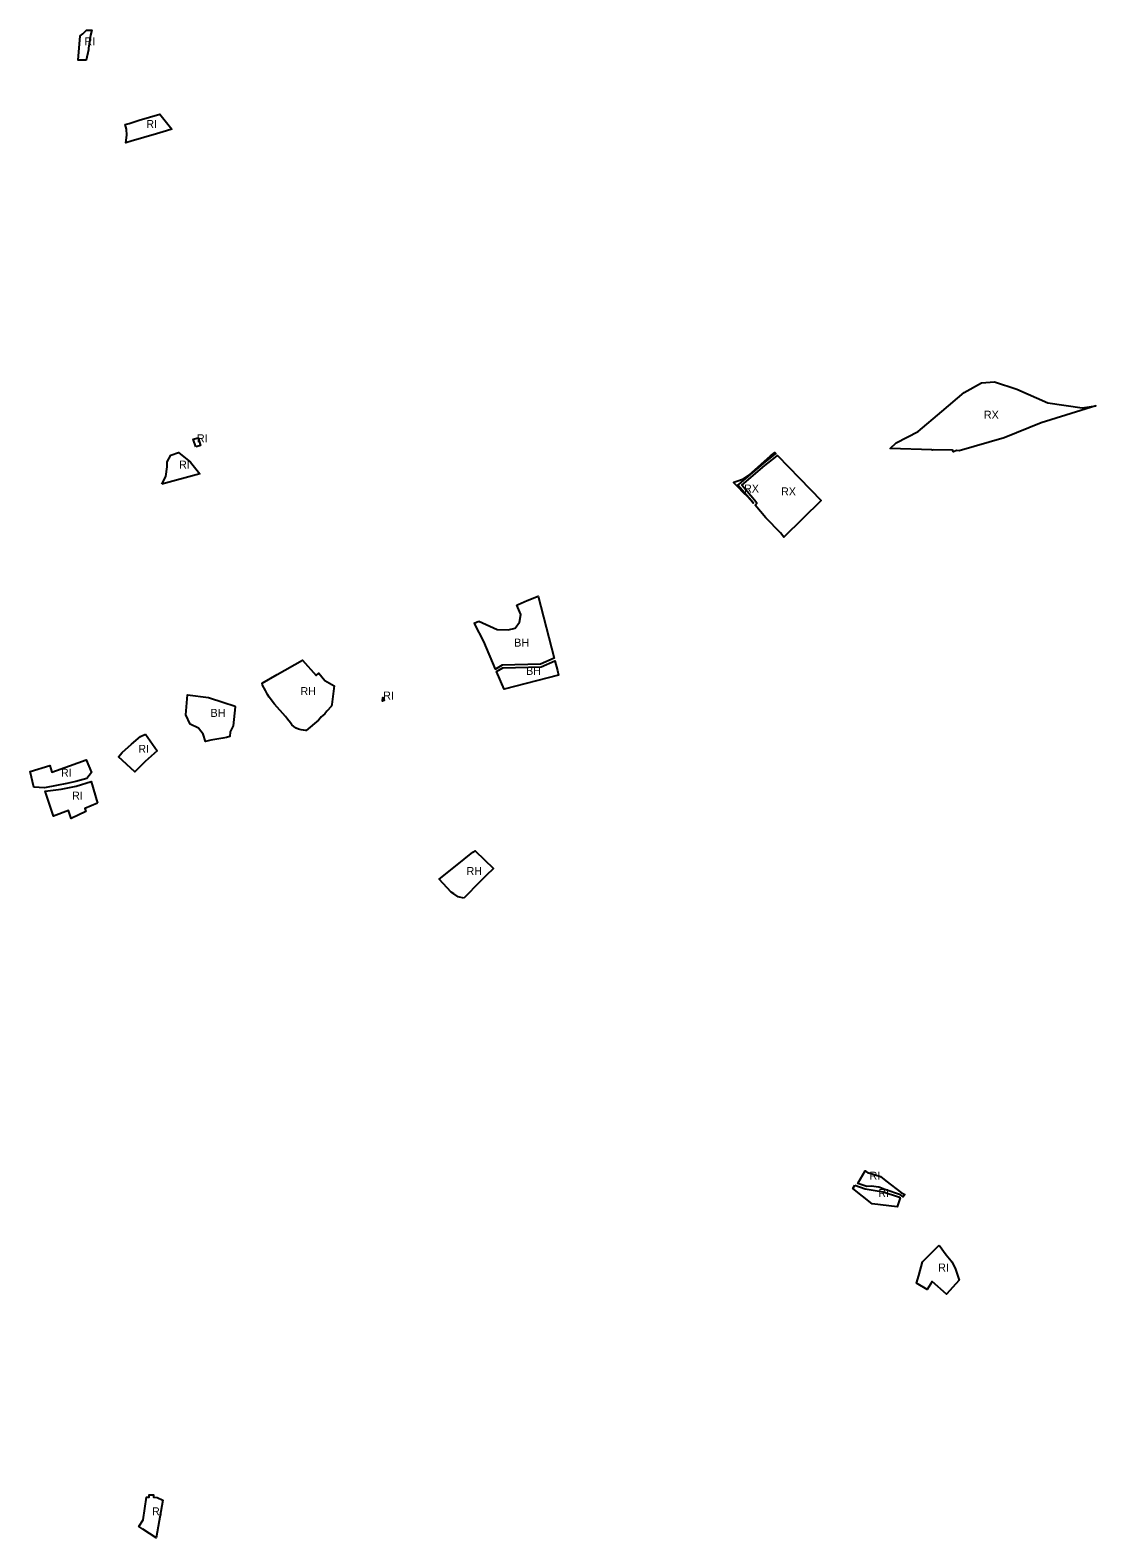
# Model space of a CAD drawing. Extents: x -477010 to -466219, y -1158799 to -1150161.
# Drawn here: x -470055 to -468854, y -1154442 to -1152743 of the extents above; entities that cross this region are included whole.
import ezdxf

# ---------------------------------------------------------------- set-up
doc = ezdxf.new("R2010")
doc.units = 0
for name, color, linetype in [('16', 7, 'Continuous'), ('19', 7, 'Continuous'), ('25', 7, 'Continuous'), ('4', 7, 'Continuous')]:
    doc.layers.add(name, color=color, linetype=linetype)

msp = doc.modelspace()

# ---------------------------------------------------------------- linework, layer by layer
at = {"layer": '16'}
for points in [[(-469720.54, -1153510.21), (-469723.07, -1153513.06), (-469725.155, -1153514.929), (-469726.93, -1153516.52), (-469727.816, -1153517.531), (-469730.11, -1153520.15), (-469744.05, -1153531.89), (-469744.58, -1153531.81), (-469747.07, -1153531.46), (-469749.61, -1153531.09), (-469752.58, -1153530.33), (-469755.37, -1153529.22), (-469757.82, -1153527.25), (-469760.03, -1153525.33), (-469761.57, -1153523.16), (-469765.13, -1153518.88), (-469767.37, -1153516.16), (-469779.49, -1153502.3), (-469785.57, -1153494.24), (-469787.54, -1153491.35), (-469789.85, -1153486.93), (-469792.99, -1153480.68), (-469793.44, -1153478.47), (-469776.53, -1153468.6), (-469748.05, -1153452.39), (-469732.51, -1153469.78), (-469729.53, -1153467.14), (-469723.09, -1153475.3), (-469712.23, -1153481.51), (-469715.09, -1153502.44), (-469715.27, -1153504.3)], [(-469566.15, -1153720.69), (-469572.52, -1153719.17), (-469577.58, -1153716.01), (-469580.51, -1153714.16), (-469594.04, -1153699.49), (-469592.71, -1153698.22), (-469566, -1153676.65), (-469556.08, -1153669.1), (-469553.54, -1153667.48), (-469532.85, -1153687.29), (-469541.02, -1153695.16), (-469548.02, -1153701.9)]]:
    msp.add_lwpolyline(points, close=True, dxfattribs=at)
at = {"layer": '19'}
for points in [[(-469995.71, -1152746.77), (-469991.28, -1152742.81), (-469985.48, -1152742.62), (-469986.82, -1152748.2), (-469989.21, -1152763.01), (-469989.19, -1152764.92), (-469991.66, -1152776.5), (-470000.793, -1152776.5), (-469998.48, -1152749.11)], [(-469931.93, -1152844.23), (-469908.87, -1152837.23), (-469895.2, -1152854.33), (-469901.47, -1152856.18), (-469912.71, -1152859.48), (-469941.19, -1152867.85), (-469946.01, -1152869.26), (-469946.95, -1152869.51), (-469946.13, -1152861.02), (-469946.48, -1152854.38), (-469947.76, -1152849.04), (-469943.36, -1152847.7)], [(-469868.32, -1153212.28), (-469871.11, -1153203.57), (-469869.68, -1153203.12), (-469865.78, -1153201.86), (-469862.99, -1153210.57), (-469866.89, -1153211.82)], [(-469906.72, -1153254.26), (-469901.96, -1153245.76), (-469900.65, -1153234.77), (-469900.55, -1153229.13), (-469896.37, -1153221.61), (-469887.78, -1153218.42), (-469874.21, -1153229.51), (-469863.88, -1153242.56)], [(-469657.02, -1153495.62), (-469656.111, -1153497.683), (-469656.017, -1153497.898), (-469657.928, -1153498.67), (-469657.911, -1153498.41), (-469657.66, -1153494.45)], [(-469925.02, -1153536.07), (-469911.73, -1153554.62), (-469925.5, -1153566.73), (-469937.01, -1153578.38), (-469955.18, -1153561.55), (-469951.31, -1153556.6), (-469940.9, -1153547.21), (-469930.65, -1153538.75)], [(-470010.45, -1153571.63), (-469991.82, -1153565.05), (-469985.61, -1153579.05), (-469990.88, -1153585.8), (-470003.56, -1153589.31), (-470013.44, -1153591.49), (-470025.19, -1153593.64), (-470038.9, -1153596.57), (-470050.73, -1153595.63), (-470054.89, -1153577.92), (-470032.88, -1153571.39), (-470030.4, -1153578.68)], [(-469979.06, -1153613.64), (-469993.46, -1153619.87), (-469992.31, -1153623.14), (-470008.62, -1153630.94), (-470011.77, -1153621.9), (-470028.64, -1153628.35), (-470037.86, -1153600.25), (-470020.14, -1153598.04), (-470003.06, -1153594.4), (-469986, -1153589.39)], [(-469112.201, -1154045.596), (-469113.553, -1154045.373), (-469122.412, -1154042.265), (-469121.9, -1154041.4), (-469114.09, -1154028.16), (-469111.12, -1154030.17), (-469110.19, -1154030.44), (-469097.07, -1154034.28), (-469090.85, -1154039.4), (-469073.3, -1154052.64), (-469069.65, -1154054.8), (-469071.23, -1154057.39), (-469074.23, -1154054.98), (-469091.98, -1154049.12), (-469098.75, -1154046.59), (-469107.56, -1154045.24)], [(-469125.96, -1154044.2), (-469114.3, -1154048.29), (-469094.05, -1154051.64), (-469076.78, -1154057.42), (-469074.81, -1154058.48), (-469078.06, -1154068.77), (-469106.28, -1154065.36), (-469127.95, -1154047.8)], [(-469030.91, -1154111.64), (-469022.77, -1154122.54), (-469017.46, -1154129.38), (-469016.63, -1154130.42), (-469012.86, -1154137.85), (-469009.23, -1154147.96), (-469008.34, -1154151.267), (-469012.05, -1154155.41), (-469022.42, -1154166.99), (-469038.6, -1154152.91), (-469044.16, -1154161.8), (-469056.15, -1154154.68), (-469053.77, -1154145.83), (-469049.63, -1154130.4), (-469031.72, -1154112.41)], [(-469927.99, -1154431.9), (-469932.55, -1154428.99), (-469927.7, -1154421.41), (-469923.65, -1154395.7), (-469921.54, -1154395.69), (-469920.88, -1154395.7), (-469920.85, -1154393.04), (-469915.95, -1154393.17), (-469916.02, -1154395.84), (-469911.87, -1154395.95), (-469905.27, -1154399.23), (-469912.803, -1154441.591)]]:
    msp.add_lwpolyline(points, close=True, dxfattribs=at)
at = {"layer": '25'}
for points in [[(-469036.74, -1153215.47), (-469038.83, -1153215.99), (-469038.97, -1153215.4), (-469085.85, -1153214.03), (-469079.18, -1153207.84), (-469054.63, -1153194.84), (-469027.77, -1153172.24), (-469002.53, -1153151.01), (-468982.94, -1153140.18), (-468968.55, -1153138.86), (-468943.46, -1153147.24), (-468908.19, -1153162.61), (-468869.52, -1153168.05), (-468854.29, -1153166.09), (-468915.81, -1153185), (-468957.67, -1153201.91), (-469008.11, -1153216.5), (-469011.38, -1153216.22), (-469014.7, -1153217.96), (-469015.68, -1153216.09)], [(-469256.488, -1153254.103), (-469257.494, -1153254.958), (-469240.073, -1153275.455), (-469240.186, -1153275.575), (-469240.79, -1153274.87), (-469246.48, -1153268.55), (-469251.48, -1153263.61), (-469256.91, -1153257.95), (-469262.57, -1153252.22), (-469262.11, -1153251.82), (-469258.76, -1153250.67), (-469251.08, -1153248.04), (-469245.3, -1153244.06), (-469220.9, -1153222.26), (-469216.075, -1153218.608), (-469214.948, -1153219.77), (-469217.287, -1153221.599), (-469229.255, -1153230.956)], [(-469188.083, -1153247.462), (-469163.836, -1153272.456), (-469205.623, -1153313.809), (-469209.66, -1153309.19), (-469226.09, -1153292.01), (-469238.222, -1153277.864), (-469236.044, -1153275.563), (-469238.854, -1153272.256), (-469253.265, -1153255.301), (-469227.358, -1153233.282), (-469215.187, -1153223.765), (-469212.847, -1153221.936)]]:
    msp.add_lwpolyline(points, close=True, dxfattribs=at)
at = {"layer": '4'}
for points in [[(-469549.339, -1153408.456), (-469528.687, -1153417.854), (-469516.294, -1153418.241), (-469516.219, -1153418.224), (-469508.515, -1153416.512), (-469503.575, -1153409.704), (-469502.263, -1153401.06), (-469506.729, -1153390.451), (-469504.959, -1153389.703), (-469495.014, -1153385.501), (-469482.61, -1153380.26), (-469464.5, -1153450.327), (-469479.759, -1153457.17), (-469523.264, -1153458.117), (-469530.547, -1153462.629), (-469543.96, -1153431.65), (-469554, -1153412.05), (-469554.021, -1153412.006), (-469554.65, -1153410.7)], [(-469479.086, -1153460.156), (-469463.738, -1153453.273), (-469460.94, -1153464.1), (-469459.57, -1153469.59), (-469520.71, -1153485.35), (-469529.342, -1153465.412), (-469522.38, -1153461.098)], [(-469833.69, -1153539.56), (-469837.88, -1153540.53), (-469851.36, -1153542.83), (-469854.36, -1153543.52), (-469857.508, -1153544.244), (-469859.91, -1153535.97), (-469865.11, -1153529.32), (-469874.62, -1153524.63), (-469879.49, -1153514.09), (-469877.726, -1153491.763), (-469854.11, -1153494.66), (-469836.68, -1153500.37), (-469824.962, -1153504.204), (-469824.146, -1153504.471), (-469823.966, -1153505.242), (-469823.968, -1153505.328), (-469826.254, -1153526.644), (-469829.726, -1153533.495), (-469829.828, -1153538.666), (-469830.064, -1153538.721)]]:
    msp.add_lwpolyline(points, close=True, dxfattribs=at)

# ---------------------------------------------------------------- texts
at = {"layer": '16'}
for p in [(-469750.3095, -1153491.953), (-469563.1975, -1153694.715)]:
    msp.add_text('RH', height=9, dxfattribs=at).set_placement(p)
at = {"layer": '19'}
for p in [(-469993.701, -1152759.768), (-469924.017, -1152852.852), (-469866.984, -1153207.067), (-469887.09, -1153236.703), (-469657.126, -1153496.965), (-469933.042, -1153556.97), (-470020.185, -1153583.909), (-470007.605, -1153609.699), (-469109.157, -1154038.04), (-469099.368, -1154057.66), (-469031.888, -1154141.454), (-469917.589, -1154416.247)]:
    msp.add_text('RI', height=9, dxfattribs=at).set_placement(p)
at = {"layer": '25'}
for p in [(-468980.3575, -1153180.497), (-469250.5795, -1153263.698), (-469208.9085, -1153266.904)]:
    msp.add_text('RX', height=9, dxfattribs=at).set_placement(p)
at = {"layer": '4'}
for p in [(-469509.4895, -1153437.278), (-469496.1275, -1153469.12), (-469851.5915, -1153516.476)]:
    msp.add_text('BH', height=9, dxfattribs=at).set_placement(p)

doc.saveas('drawing.dxf')
